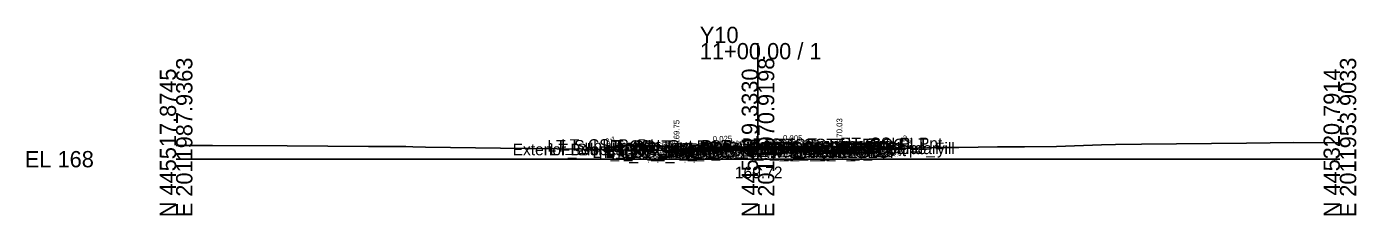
# Model space of a CAD drawing. Extents: x -26 to 203, y -10 to 3517.
# Drawn here: x -25.7 to 202.8, y 1990.3 to 2022.8 of the extents above; entities that cross this region are included whole.
import ezdxf

# ---------------------------------------------------------------- set-up
doc = ezdxf.new("R2010")
doc.units = 0
for name, color, linetype in [('Default', 7, 'Continuous'), ('Exist CMT Pavement', 7, 'Continuous'), ('Exist Cross Section Cell', 7, 'Continuous'), ('Exist XS Center Line Elevation Label', 7, 'Continuous'), ('Exist XS Ground Line', 7, 'Continuous'), ('Prop CMT Conc Surface', 7, 'Continuous'), ('Prop CMT Concrete Structures', 7, 'Continuous'), ('Prop CMT Pvmt Course 1', 7, 'Continuous'), ('Prop CMT Pvmt Course 1 CG', 7, 'Continuous'), ('Prop CMT Pvmt Course 1 Wedge', 7, 'Continuous'), ('Prop CMT Pvmt Course 2', 7, 'Continuous'), ('Prop CMT Pvmt Course 2 Wedge', 7, 'Continuous'), ('Prop CMT Pvmt Course 3', 7, 'Continuous'), ('Prop CMT Pvmt Course 3 Wedge', 7, 'Continuous'), ('Prop CMT Pvmt Surface', 7, 'Continuous'), ('Prop CMT Pvmt Wedge Surface 1', 7, 'Continuous'), ('Prop CMT Pvmt Wedge Surface 2', 7, 'Continuous'), ('Prop CMT Pvmt Wedge Surface 3', 7, 'Continuous'), ('Prop CMT Slope Grass', 7, 'Continuous'), ('Prop CMT Subgrade Earthwork', 7, 'Continuous'), ('Prop XS Earthwork Shape', 7, 'Continuous'), ('Prop XS Hydro Elevations', 7, 'Continuous'), ('Prop XS SE Text', 7, 'Continuous'), ('Prop XS Side Slope Text', 7, 'Continuous'), ('Prop XS Wedging', 7, 'Continuous'), ('Scratch_Level_0', 7, 'Continuous')]:
    doc.layers.add(name, color=color, linetype=linetype)

msp = doc.modelspace()

# ---------------------------------------------------------------- linework, layer by layer
at = {"layer": 'Exist CMT Pavement'}
for points in [[(100, 2001.72), (99.3, 2001.75), (90.74, 2001.48), (89, 2001.43)], [(100, 2001.72), (102.13, 2001.65), (111, 2001.32)]]:
    msp.add_lwpolyline(points, dxfattribs=at)
at = {"layer": 'Exist Cross Section Cell'}
for p, q in [((100, 2000), (100, 2020)), ((0, 2000), (100, 2000)), ((100, 2000), (200, 2000))]:
    msp.add_line(p, q, dxfattribs=at)
at = {"layer": 'Exist XS Ground Line'}
msp.add_lwpolyline([(0, 2002.34), (1.83, 2002.34), (6.24, 2002.34), (19.08, 2002.29), (33.05, 2002.2), (37.32, 2002.16), (38.24, 2002.17), (39.5, 2002.16), (40.69, 2002.1), (42.85, 2002.08), (55.73, 2001.91), (59.94, 2001.84), (60.89, 2001.82), (70.09, 2001.75), (80.01, 2001.53), (87.21, 2001.5), (88.27, 2001.4), (90.74, 2001.48), (99.3, 2001.75), (100, 2001.72), (102.13, 2001.65), (111.67, 2001.29), (112.83, 2001.44), (116.43, 2001.52), (123.06, 2001.76), (130.99, 2002), (134.49, 2002.01), (141.14, 2002.12), (145.82, 2002.14), (151.28, 2002.18), (159.03, 2002.45), (161.43, 2002.54), (165.9, 2002.61), (183.96, 2002.77), (192.11, 2002.85), (197.75, 2002.83), (200, 2002.88)], dxfattribs=at)
at = {"layer": 'Prop CMT Conc Surface'}
for points in [[(86, 2001.75), (86, 2002.25), (85.5, 2002.25)], [(112, 2002.12), (114, 2002.03)], [(114, 2002.03), (114, 2002.53), (114.5, 2002.53)], [(88, 2001.88), (86, 2001.75)]]:
    msp.add_lwpolyline(points, dxfattribs=at)
at = {"layer": 'Prop CMT Concrete Structures'}
for points in [[(88, 2001.88), (86, 2001.75), (86, 2002.25), (85.5, 2002.25)], [(85.5, 2002.25), (85.5, 2001.23), (88, 2001.3)], [(112, 2002.12), (114, 2002.03), (114, 2002.53), (114.5, 2002.53)], [(114.5, 2002.53), (114.5, 2001.52), (112, 2001.54)], [(112, 2001.54), (112, 2002.12)], [(88, 2001.3), (88, 2001.88)]]:
    msp.add_lwpolyline(points, dxfattribs=at)
at = {"layer": 'Prop CMT Pvmt Course 1'}
for points in [[(100, 2002.18), (88, 2001.88)], [(89, 2001.78), (100, 2002.06)], [(100, 2001.93), (100, 2002.18)], [(100, 2002.18), (112, 2002.12)], [(100, 2001.93), (100, 2002.18)], [(100, 2002.06), (100, 2001.93), (100, 2001.93)], [(111, 2002), (100, 2002.06)], [(100, 2002.06), (100, 2001.93), (100, 2001.93)], [(111, 2001.88), (111, 2002)], [(112, 2002.12), (112, 2001.87)], [(88, 2001.88), (88, 2001.63)], [(88, 2001.63), (89, 2001.66)], [(89, 2001.66), (89, 2001.78)], [(112, 2001.87), (111, 2001.88)]]:
    msp.add_lwpolyline(points, dxfattribs=at)
at = {"layer": 'Prop CMT Pvmt Course 1 CG'}
for points in [[(88, 2001.3), (85, 2001.22), (84.66, 2000.88)], [(84.66, 2000.88), (88, 2000.96)], [(88, 2000.96), (88, 2001.3)], [(112, 2001.54), (115, 2001.52), (115.33, 2001.19)], [(112, 2001.2), (112, 2001.54)], [(115.33, 2001.19), (112, 2001.2)]]:
    msp.add_lwpolyline(points, dxfattribs=at)
at = {"layer": 'Prop CMT Pvmt Course 1 Wedge'}
for points in [[(89, 2001.78), (90.74, 2001.82), (99.3, 2002.04), (100, 2002.06)], [(100, 2002.06), (100, 2001.93)], [(100, 2002.06), (102.13, 2002.04), (111, 2002)], [(100, 2001.93), (100, 2002.06)], [(111, 2002), (111, 2001.88)], [(100, 2001.93), (99.3, 2001.91), (90.74, 2001.7), (89, 2001.66)], [(89, 2001.66), (89, 2001.78)], [(111, 2001.88), (102.13, 2001.92), (100, 2001.93)]]:
    msp.add_lwpolyline(points, dxfattribs=at)
at = {"layer": 'Prop CMT Pvmt Course 2'}
for points in [[(89, 2001.66), (88, 2001.63)], [(88, 2001.63), (88, 2001.3)], [(88, 2001.3), (89, 2001.32)], [(89, 2001.32), (89, 2001.66)], [(111, 2001.54), (111, 2001.88)], [(111, 2001.88), (112, 2001.87)], [(112, 2001.54), (111, 2001.54)], [(112, 2001.87), (112, 2001.54)]]:
    msp.add_lwpolyline(points, dxfattribs=at)
at = {"layer": 'Prop CMT Pvmt Course 2 Wedge'}
for points in [[(89, 2001.66), (90.74, 2001.7), (99.3, 2001.91), (100, 2001.93)], [(89, 2001.66), (90.74, 2001.7), (99.3, 2001.91), (100, 2001.93)], [(100, 2001.72), (99.3, 2001.75), (90.74, 2001.48), (89, 2001.43)], [(100, 2001.72), (99.3, 2001.75), (90.74, 2001.48), (89, 2001.43)], [(89, 2001.43), (89, 2001.66)], [(89, 2001.43), (89, 2001.66)], [(100, 2001.93), (100, 2001.72)], [(100, 2001.93), (100, 2001.72)], [(100, 2001.93), (102.13, 2001.92), (111, 2001.88)], [(100, 2001.72), (100, 2001.93)], [(100, 2001.93), (102.13, 2001.92), (111, 2001.88)], [(100, 2001.72), (100, 2001.93)], [(111, 2001.54), (104, 2001.58), (102.13, 2001.65), (100, 2001.72)], [(111, 2001.63), (102.13, 2001.67), (101.38, 2001.67), (100, 2001.72)], [(111, 2001.88), (111, 2001.54)], [(111, 2001.88), (111, 2001.63)]]:
    msp.add_lwpolyline(points, dxfattribs=at)
at = {"layer": 'Prop CMT Pvmt Course 3'}
for points in [[(89, 2001.32), (88, 2001.3)], [(88, 2001.3), (88, 2000.96)], [(88, 2000.96), (89, 2000.99)], [(89, 2000.99), (89, 2001.32)], [(111, 2001.54), (112, 2001.54)], [(111, 2001.21), (111, 2001.54)], [(112, 2001.2), (111, 2001.21)], [(112, 2001.54), (112, 2001.2)]]:
    msp.add_lwpolyline(points, dxfattribs=at)
at = {"layer": 'Prop CMT Pvmt Course 3 Wedge'}
for points in [[(111, 2001.32), (104, 2001.58)], [(104, 2001.58), (111, 2001.54)], [(111, 2001.54), (111, 2001.32)]]:
    msp.add_lwpolyline(points, dxfattribs=at)
at = {"layer": 'Prop CMT Pvmt Surface'}
for points in [[(100, 2002.18), (88, 2001.88)], [(100, 2002.18), (112, 2002.12)]]:
    msp.add_lwpolyline(points, dxfattribs=at)
at = {"layer": 'Prop CMT Pvmt Wedge Surface 1'}
for points in [[(100, 2002.06), (89, 2001.78)], [(100, 2002.06), (111, 2002)], [(111, 2002), (111, 2001.88)], [(112, 2001.87), (112, 2002.12)], [(88, 2001.63), (88, 2001.88)], [(89, 2001.66), (88, 2001.63)], [(89, 2001.78), (89, 2001.66)], [(111, 2001.88), (112, 2001.87)]]:
    msp.add_lwpolyline(points, dxfattribs=at)
at = {"layer": 'Prop CMT Pvmt Wedge Surface 2'}
for points in [[(112, 2001.87), (112, 2002.12)], [(100, 2001.93), (88, 2001.63)], [(88, 2001.63), (88, 2001.88)], [(100, 2001.93), (112, 2001.87)]]:
    msp.add_lwpolyline(points, dxfattribs=at)
at = {"layer": 'Prop CMT Pvmt Wedge Surface 3'}
for points in [[(112, 2001.54), (112, 2002.12)], [(88, 2001.3), (88, 2001.88)], [(100, 2001.6), (88, 2001.3)], [(100, 2001.6), (112, 2001.54)]]:
    msp.add_lwpolyline(points, dxfattribs=at)
at = {"layer": 'Prop CMT Slope Grass'}
for points in [[(85.5, 2002.25), (76, 2002.44), (73.69, 2001.67)], [(114.5, 2002.53), (124, 2002.72), (126.56, 2001.87)]]:
    msp.add_lwpolyline(points, dxfattribs=at)
at = {"layer": 'Prop CMT Subgrade Earthwork'}
for points in [[(88, 2000.96), (84.66, 2000.88), (83.24, 2002.3)], [(112, 2001.2), (115.33, 2001.19), (116.72, 2002.57)], [(89, 2000.99), (88, 2000.96)], [(89, 2000.99), (89.01, 2001.43)], [(111, 2001.21), (110.98, 2001.32)], [(111, 2001.21), (112, 2001.2)]]:
    msp.add_lwpolyline(points, dxfattribs=at)
at = {"layer": 'Prop XS Earthwork Shape'}
for points in [[(84.03, 2001.51), (83.24, 2002.3), (76, 2002.44), (73.69, 2001.67), (80.01, 2001.53)], [(124, 2002.72), (126.56, 2001.87), (123.06, 2001.76), (116.43, 2001.52), (115.65, 2001.5), (116.72, 2002.57)], [(84.66, 2000.88), (84.03, 2001.51), (85.5, 2001.5), (85.5, 2001.23), (88, 2001.3), (88, 2001.43), (88.27, 2001.4), (89, 2001.43), (89.01, 2001.43), (89, 2000.99), (88, 2000.96)], [(87.21, 2001.5), (88, 2001.43), (88, 2001.3), (85.5, 2001.23), (85.5, 2001.5)], [(111, 2001.21), (110.98, 2001.32), (111, 2001.32), (111.67, 2001.29), (112.83, 2001.44), (115.65, 2001.5), (115.33, 2001.19), (112, 2001.2)]]:
    msp.add_lwpolyline(points, close=True, dxfattribs=at)
at = {"layer": 'Prop XS Wedging'}
for p, q in [((99.3, 2002.04), (90.74, 2001.82)), ((100, 2002.06), (99.3, 2002.04)), ((102.13, 2002.04), (100, 2002.06)), ((100, 2002.06), (100, 2001.93)), ((100, 2001.93), (100, 2002.06)), ((111, 2002), (102.13, 2002.04)), ((111, 2001.88), (111, 2002)), ((90.74, 2001.82), (89, 2001.78)), ((89, 2001.78), (89, 2001.66)), ((89, 2001.66), (89.17, 2001.66)), ((89.17, 2001.66), (89, 2001.66)), ((89, 2001.66), (89, 2001.43)), ((89, 2001.43), (89.01, 2001.43)), ((89.01, 2001.43), (90.74, 2001.48)), ((89.17, 2001.66), (90.74, 2001.7)), ((90.74, 2001.48), (92.2, 2001.53)), ((92, 2001.73), (91.62, 2001.72)), ((92.2, 2001.53), (92, 2001.73)), ((92, 2001.73), (92.2, 2001.53)), ((92.2, 2001.53), (92, 2001.73)), ((100, 2001.93), (100, 2001.72)), ((100.24, 2001.93), (100, 2001.93)), ((100, 2001.72), (100, 2001.93)), ((100, 2001.72), (100.04, 2001.72)), ((100.04, 2001.72), (100.24, 2001.93)), ((100.04, 2001.72), (100.24, 2001.93)), ((100.24, 2001.93), (100.04, 2001.72)), ((100.04, 2001.72), (101.38, 2001.67)), ((101.84, 2001.92), (100.24, 2001.93)), ((101.38, 2001.67), (102.13, 2001.65)), ((109.37, 2001.55), (104, 2001.58)), ((104, 2001.58), (109.2, 2001.38)), ((111, 2001.88), (108.16, 2001.89)), ((109.2, 2001.38), (109.45, 2001.63)), ((109.2, 2001.38), (109.37, 2001.55)), ((109.37, 2001.55), (109.2, 2001.38)), ((109.2, 2001.38), (110.98, 2001.32)), ((109.37, 2001.55), (109.45, 2001.63)), ((109.45, 2001.63), (109.37, 2001.55)), ((109.37, 2001.55), (111, 2001.54)), ((111, 2001.54), (109.37, 2001.55)), ((111, 2001.63), (109.45, 2001.63)), ((110.98, 2001.32), (111, 2001.32)), ((111, 2001.63), (111, 2001.88)), ((111, 2001.54), (111, 2001.63)), ((111, 2001.32), (111, 2001.54))]:
    msp.add_line(p, q, dxfattribs=at)
for points in [[(91.62, 2001.72), (90.74, 2001.7), (89.17, 2001.66)], [(90.74, 2001.7), (92, 2001.73), (99.3, 2001.91), (100, 2001.93)], [(100, 2001.93), (99.3, 2001.91), (98.21, 2001.89), (92, 2001.73)], [(92.2, 2001.53), (99.3, 2001.75), (100, 2001.72)], [(100, 2001.93), (100.24, 2001.93), (102.13, 2001.92)], [(101.38, 2001.67), (102.13, 2001.67), (109.45, 2001.63), (111, 2001.63)], [(109.45, 2001.63), (102.13, 2001.67), (101.38, 2001.67)], [(108.16, 2001.89), (102.13, 2001.92), (101.84, 2001.92)], [(102.13, 2001.92), (108.16, 2001.89), (111, 2001.88)], [(102.13, 2001.65), (104, 2001.58), (109.37, 2001.55)]]:
    msp.add_lwpolyline(points, dxfattribs=at)

# ---------------------------------------------------------------- texts
at = {"layer": 'Default'}
msp.add_text('-', height=0.0001, dxfattribs=at).set_placement((0, 2000))
at = {"layer": 'Exist Cross Section Cell'}
for s, p in [('Y10', (90, 2020)), ('11+00.00 / 1', (90, 2017.2)), ('EL 168', (-26, 1998.6))]:
    msp.add_text(s, height=2.8, dxfattribs=at).set_placement(p)
for s, p in [('E 2011987.9363', (2.8, 1990)), ('E 2011970.9198', (102.8, 1990)), ('E 2011953.9033', (202.8, 1990)), ('N 445517.8745', (0, 1990)), ('N 445419.3330', (100, 1990)), ('N 445320.7914', (200, 1990))]:
    msp.add_text(s, height=2.8, rotation=90, dxfattribs=at).set_placement(p)
at = {"layer": 'Exist XS Center Line Elevation Label'}
msp.add_text('169.72', height=2, dxfattribs=at).set_placement((96.03, 1996.72))
at = {"layer": 'Prop XS Hydro Elevations'}
for s, p in [('169.75', (86.5, 2002.68)), ('170.03', (114.5, 2002.96))]:
    msp.add_text(s, height=1, rotation=90, dxfattribs=at).set_placement(p)
at = {"layer": 'Prop XS SE Text'}
for s, rotation, p in [('0.025', 1.7184, (92.24, 2002.95)), ('0.005', 359.4271, (104.28, 2003.14))]:
    msp.add_text(s, height=1, rotation=rotation, dxfattribs=at).set_placement(p)
at = {"layer": 'Prop XS Side Slope Text'}
for rotation, p in [(18.4332, (73.95, 2002.48)), (341.5668, (124.67, 2003.22))]:
    msp.add_text('3:1', height=1, rotation=rotation, dxfattribs=at).set_placement(p)
at = {"layer": 'Scratch_Level_0'}
for s, p in [('Exterior Boundary', (57.83, 2000.67)), ('LT_Sub_Trench_Out_DLT', (63.81, 2001.3)), ('LT_Slope_Fill', (64.21, 2000.67)), ('LT_CSLP_Pnt', (66.17, 2001.44)), ('LT_CG1_Shelf_Out', (71.55, 2000.22)), ('LT_CG_Top_Face', (73.26, 2001.25)), ('LT_CG_Top_BOC', (73.78, 2001.25)), ('LT_CG_Bot_BOC', (73.81, 2000.23)), ('LT_PV_Sub_Tie_Out', (73.96, 2000.43)), ('LT_CG_Top_Gut', (74.24, 2000.75)), ('LT_Sub_OEOP', (74.77, 1999.88)), ('LT_PV_OEEOP_EG', (76.54, 2000.43)), ('LT_CG_Bot_IE', (77.91, 2000.3)), ('LT_Sub_OEOT', (78.08, 1999.96)), ('LT_PV2_OEOT', (78.17, 2000.63)), ('LT_PV3_OEOT', (78.17, 2000.3)), ('LT_Sub_OEEOP', (78.21, 1999.99)), ('LT_PV2_OEEOP', (78.31, 2000.66)), ('LT_PV3_OEEOP', (78.31, 2000.32)), ('LT_PV1_OEOT', (78.74, 2000.88)), ('LT_PV1_OEEOP', (78.87, 2000.78)), ('RT_PV_IEEOP_EG', (88.14, 2000.72)), ('LT_PV_IEEOP_EG', (88.19, 2000.72)), ('RT_PV2_IEEOP', (89.91, 2000.93)), ('RT_PV3_IEEOP', (89.91, 2000.6)), ('LT_PV2_IEEOP', (89.95, 2000.93)), ('LT_PV3_IEEOP', (89.95, 2000.6)), ('RT_PV1_IEEOP', (90.47, 2001.06)), ('LT_PV1_IEEOP', (90.52, 2001.06)), ('PV2_PGL', (93.91, 2000.93)), ('PV1_PGL', (94.47, 2001.18)), ('RT_PV_Sub_Tie_Out', (95.88, 2000.32)), ('RT_Sub_Trench_Out_DLT', (97.24, 2001.57)), ('RT_PV_OEEOP_EG', (98.5, 2000.32)), ('RT_Sub_OEEOP', (100.17, 2000.21)), ('RT_PV2_OEEOP', (100.26, 2000.88)), ('RT_PV3_OEEOP', (100.26, 2000.54)), ('RT_PV1_OEEOP', (100.83, 2001)), ('RT_CG_Top_Face', (101.21, 2001.53)), ('RT_CG1_Shelf_Out', (101.5, 2000.52)), ('RT_CG_Bot_IE', (101.87, 2000.54)), ('RT_Sub_OEOT', (102.03, 2000.2)), ('RT_PV2_OEOT', (102.13, 2000.87)), ('RT_PV3_OEOT', (102.13, 2000.54)), ('RT_CG_Top_Gut', (102.19, 2001.03)), ('RT_PV1_OEOT', (102.69, 2001.12)), ('RT_CG_Top_BOC', (102.74, 2001.53)), ('RT_CG_Bot_BOC', (102.77, 2000.52)), ('RT_Sub_OEOP', (105.4, 2000.19)), ('Exterior Boundary', (110.7, 2000.87)), ('RT_CSLP_Pnt', (114.13, 2001.72)), ('RT_Slope_Fill', (117.03, 2000.87))]:
    msp.add_text(s, height=2, dxfattribs=at).set_placement(p)

doc.saveas('drawing.dxf')
